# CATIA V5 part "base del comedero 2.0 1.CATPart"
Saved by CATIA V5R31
Part number: base del comedero 2.0
Bounding box of the stored display mesh (mm): x -244 to 244, y -89 to 89, z 0 to 15
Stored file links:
  C:\Users\189361\Desktop\piezas del comedero\piezas del comedero\base del comedero 2.0 1.CATPart
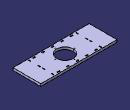
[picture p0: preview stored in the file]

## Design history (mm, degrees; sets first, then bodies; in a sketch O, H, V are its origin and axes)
Body1 (main body)
  Sketch1 on xy-plane, origin (0, 0, 0), H (1, 0, 0), V (0, 1, 0)
    circle A1 centre (0, 0) radius 53
    circle A2 centre (0, 62.25) radius 2.25
    point P1 (0, 62.25)
    circle A3 centre (62.25, 0) radius 2.25
    point P2 (62.25, 0)
    circle A4 centre (0, -62.25) radius 2.25
    circle A5 centre (-62.25, 0) radius 2.25
    line L1 (-164, 89) -> (164, 89)
    line L2 (164, 89) -> (164, -89)
    line L3 (164, -89) -> (-164, -89)
    line L4 (-164, -89) -> (-164, 89)
    point P9 (-153.3, 81.6)
    line L5 (-153.3, 81.6) -> (-150, 81.6)
    line L6 (-150, 81.6) -> (-150, 66.6)
    line L7 (-150, 66.6) -> (-153.3, 66.6)
    line L8 (-153.3, 66.6) -> (-153.3, 81.6)
    point P10 (-150, 81.6)
    point P11 (-150, 66.6)
    point P12 (-153.3, 66.6)
    point P13 (-127.5, 81.6)
    line L9 (-127.5, 81.6) -> (-112.5, 81.6)
    line L10 (-112.5, 81.6) -> (-112.5, 75)
    line L11 (-112.5, 75) -> (-127.5, 75)
    line L12 (-127.5, 75) -> (-127.5, 81.6)
    point P14 (-112.5, 81.6)
    point P15 (-112.5, 75)
    point P16 (-127.5, 75)
    construction line L13 (-120, 64.0681) -> (-120, 97.6973)
    point P17 (-120, 64.0681)
    point P18 (-120, 97.6973)
    construction line L14 (-169.6083, 74.1) -> (-149.5524, 74.1)
    point P19 (-169.6083, 74.1)
    point P20 (-149.5524, 74.1)
    construction line L15 (-166.5695, 44.1) -> (-141.0438, 44.1)
    point P21 (-166.5695, 44.1)
    point P22 (-141.0438, 44.1)
    point P23 (-153.3, 6.6)
    point P24 (-150, 6.6)
    point P25 (-150, 21.6)
    point P26 (-153.3, 21.6)
    point P27 (-169.6083, 14.1)
    point P28 (-149.5524, 14.1)
    construction line L16 (-169.6083, 14.1) -> (-149.5524, 14.1)
    line L17 (-153.3, 6.6) -> (-150, 6.6)
    line L18 (-150, 6.6) -> (-150, 21.6)
    line L19 (-150, 21.6) -> (-153.3, 21.6)
    line L20 (-153.3, 21.6) -> (-153.3, 6.6)
    axis line L21 (-90, 102.762) -> (-90, 66.7018)
    point P29 (-90, 102.762)
    point P30 (-90, 66.7018)
    point P31 (-52.5, 81.6)
    point P32 (-67.5, 81.6)
    point P33 (-67.5, 75)
    point P34 (-52.5, 75)
    point P35 (-60, 97.6973)
    point P36 (-60, 64.0681)
    construction line L22 (-60, 64.0681) -> (-60, 97.6973)
    line L23 (-52.5, 81.6) -> (-67.5, 81.6)
    line L24 (-67.5, 81.6) -> (-67.5, 75)
    line L25 (-67.5, 75) -> (-52.5, 75)
    line L26 (-52.5, 75) -> (-52.5, 81.6)
    point P37 (-153.3, -81.6)
    point P38 (-150, -81.6)
    point P39 (-150, -66.6)
    point P40 (-153.3, -66.6)
    point P41 (-149.5524, -74.1)
    point P42 (-169.6083, -74.1)
    construction line L27 (-169.6083, -74.1) -> (-149.5524, -74.1)
    point P43 (-141.0438, -44.1)
    point P44 (-166.5695, -44.1)
    construction line L28 (-166.5695, -44.1) -> (-141.0438, -44.1)
    point P45 (-153.3, -6.6)
    point P46 (-150, -6.6)
    point P47 (-150, -21.6)
    point P48 (-153.3, -21.6)
    point P49 (-169.6083, -14.1)
    point P50 (-149.5524, -14.1)
    construction line L29 (-169.6083, -14.1) -> (-149.5524, -14.1)
    line L30 (-153.3, -81.6) -> (-150, -81.6)
    line L31 (-150, -81.6) -> (-150, -66.6)
    line L32 (-150, -66.6) -> (-153.3, -66.6)
    line L33 (-153.3, -66.6) -> (-153.3, -81.6)
    line L34 (-153.3, -6.6) -> (-150, -6.6)
    line L35 (-150, -6.6) -> (-150, -21.6)
    line L36 (-150, -21.6) -> (-153.3, -21.6)
    line L37 (-153.3, -21.6) -> (-153.3, -6.6)
    point P51 (153.3, 6.6)
    point P52 (150, 6.6)
    point P53 (150, 21.6)
    point P54 (153.3, 21.6)
    point P55 (149.5524, 14.1)
    point P56 (153.3, -81.6)
    point P57 (150, -81.6)
    point P58 (150, -66.6)
    point P59 (153.3, -66.6)
    point P60 (149.5524, -74.1)
    point P61 (153.3, -6.6)
    point P62 (150, -6.6)
    point P63 (150, -21.6)
    point P64 (153.3, -21.6)
    point P65 (149.5524, -14.1)
    line L38 (153.3, 6.6) -> (150, 6.6)
    line L39 (150, 6.6) -> (150, 21.6)
    line L40 (150, 21.6) -> (153.3, 21.6)
    line L41 (153.3, 21.6) -> (153.3, 6.6)
    line L42 (153.3, -81.6) -> (150, -81.6)
    line L43 (150, -81.6) -> (150, -66.6)
    line L44 (150, -66.6) -> (153.3, -66.6)
    line L45 (153.3, -66.6) -> (153.3, -81.6)
    line L46 (153.3, -6.6) -> (150, -6.6)
    line L47 (150, -6.6) -> (150, -21.6)
    line L48 (150, -21.6) -> (153.3, -21.6)
    line L49 (153.3, -21.6) -> (153.3, -6.6)
    point P66 (153.3, 81.6)
    point P67 (150, 81.6)
    point P68 (149.5524, 74.1)
    line L50 (153.3, 81.6) -> (150, 81.6)
    point P69 (150, 66.6)
    line L51 (150, 81.6) -> (150, 66.6)
    point P70 (153.3, 66.6)
    line L52 (153.3, 66.6) -> (153.3, 81.6)
    line L53 (150, 66.6) -> (153.3, 66.6)
    point P71 (127.5, 81.6)
    point P72 (112.5, 81.6)
    point P73 (112.5, 75)
    point P74 (127.5, 75)
    point P75 (120, 97.6973)
    point P76 (120, 64.0681)
    construction line L54 (120, 64.0681) -> (120, 97.6973)
    point P77 (90, 66.7018)
    point P78 (90, 102.762)
    construction line L55 (90, 102.762) -> (90, 66.7018)
    point P79 (52.5, 81.6)
    point P80 (67.5, 81.6)
    point P81 (67.5, 75)
    point P82 (52.5, 75)
    point P83 (60, 97.6973)
    point P84 (60, 64.0681)
    construction line L56 (60, 64.0681) -> (60, 97.6973)
    line L57 (127.5, 81.6) -> (112.5, 81.6)
    line L58 (112.5, 81.6) -> (112.5, 75)
    line L59 (112.5, 75) -> (127.5, 75)
    line L60 (127.5, 75) -> (127.5, 81.6)
    line L61 (52.5, 81.6) -> (67.5, 81.6)
    line L62 (67.5, 81.6) -> (67.5, 75)
    line L63 (67.5, 75) -> (52.5, 75)
    line L64 (52.5, 75) -> (52.5, 81.6)
    point P85 (-127.5, -81.6)
    point P86 (-112.5, -81.6)
    point P87 (-112.5, -75)
    point P88 (-127.5, -75)
    point P89 (-52.5, -81.6)
    point P90 (-67.5, -81.6)
    point P91 (-67.5, -75)
    point P92 (-52.5, -75)
    point P93 (127.5, -81.6)
    point P94 (112.5, -81.6)
    point P95 (112.5, -75)
    point P96 (127.5, -75)
    point P97 (52.5, -81.6)
    point P98 (67.5, -81.6)
    point P99 (67.5, -75)
    point P100 (52.5, -75)
    line L65 (-127.5, -81.6) -> (-112.5, -81.6)
    line L66 (-112.5, -81.6) -> (-112.5, -75)
    line L67 (-112.5, -75) -> (-127.5, -75)
    line L68 (-127.5, -75) -> (-127.5, -81.6)
    line L69 (-52.5, -81.6) -> (-67.5, -81.6)
    line L70 (-67.5, -81.6) -> (-67.5, -75)
    line L71 (-67.5, -75) -> (-52.5, -75)
    line L72 (-52.5, -75) -> (-52.5, -81.6)
    line L73 (127.5, -81.6) -> (112.5, -81.6)
    line L74 (112.5, -81.6) -> (112.5, -75)
    line L75 (112.5, -75) -> (127.5, -75)
    line L76 (127.5, -75) -> (127.5, -81.6)
    line L77 (52.5, -81.6) -> (67.5, -81.6)
    line L78 (67.5, -81.6) -> (67.5, -75)
    line L79 (67.5, -75) -> (52.5, -75)
    line L80 (52.5, -75) -> (52.5, -81.6)
    point P101 (-7.5, 81.6)
    line L81 (-7.5, 81.6) -> (7.5, 81.6)
    line L82 (7.5, 81.6) -> (7.5, 75.6)
    line L83 (7.5, 75.6) -> (-7.5, 75.6)
    line L84 (-7.5, 75.6) -> (-7.5, 81.6)
    point P102 (7.5, 81.6)
    point P103 (7.5, 75.6)
    point P104 (-7.5, 75.6)
    point P105 (-7.5, -81.6)
    point P106 (7.5, -81.6)
    point P107 (7.5, -75.6)
    point P108 (-7.5, -75.6)
    line L85 (-7.5, -81.6) -> (7.5, -81.6)
    line L86 (7.5, -81.6) -> (7.5, -75.6)
    line L87 (7.5, -75.6) -> (-7.5, -75.6)
    line L88 (-7.5, -75.6) -> (-7.5, -81.6)
    radius A1 = 53
    radius A2 = 2.25
    distance A1 A2 = 7
    distance A1 A3 = 7
    length L1 = 328
    length L2 = 178
    distance H L1 = 89
    distance V L2 = 164
    length L5 = 3.3
    length L8 = 15
    length L9 = 15
    length L12 = 6.6
    distance L8 L4 = 10.7
    distance L9 L1 = 7.4
    distance L13 L10 = 7.5
    distance L13 L6 = 30
    distance L14 L5 = 7.5
    distance L15 L14 = 30
    distance L13 L21 = 30
    length L81 = 15
    length L84 = 6
    distance V L82 = 7.5
    distance L31 L43 = 300 (reference)
    distance L75 L59 = 150 (reference)
    distance L73 L57 = 163.2 (reference)
    distance V A3 = 64.5 (reference)
    distance L75 L59 = 150 (reference)
    distance P2 O = 62.25 (reference)
    coincidence: P1 V, P2 H, L5 L9, L81 L23
    equal size: A2 A3
    symmetry: A2 A4 H, A3 A5 V, P9 P23 L15, P10 P24 L15, P11 P25 L15, P12 P26 L15, P19 P27 L15, P20 P28 L15, L14 L16 L15, L5 L17 L15, L6 L18 L15, L7 L19 L15, L8 L20 L15, P13 P31 L21, P14 P32 L21, P15 P33 L21, P16 P34 L21, P18 P35 L21, P17 P36 L21, L13 L22 L21, L9 L23 L21, L10 L24 L21, L11 L25 L21, L12 L26 L21, P9 P37 H, P10 P38 H, P11 P39 H, P12 P40 H, P20 P41 H, P19 P42 H, L14 L27 H, P22 P43 H, P21 P44 H, L15 L28 H, P23 P45 H, P24 P46 H, P25 P47 H, P26 P48 H, P27 P49 H, P28 P50 H, L16 L29 H, L5 L30 H, L6 L31 H, L7 L32 H, L8 L33 H, L17 L34 H, L18 L35 H, L19 L36 H, L20 L37 H, P23 P51 V, P24 P52 V, P25 P53 V, P26 P54 V, P28 P55 V, P37 P56 V, P38 P57 V, P39 P58 V, P40 P59 V, P41 P60 V, P45 P61 V, P46 P62 V, P47 P63 V, P48 P64 V, P50 P65 V, L17 L38 V, L18 L39 V, L19 L40 V, L20 L41 V, L30 L42 V, L31 L43 V, L32 L44 V, L33 L45 V, L34 L46 V, L35 L47 V, L36 L48 V, L37 L49 V, P9 P66 V, P10 P67 V, P20 P68 V, L5 L50 V, P11 P69 V, L6 L51 V, P12 P70 V, L8 L52 V, L7 L53 V, P13 P71 V, P14 P72 V, P15 P73 V, P16 P74 V, P18 P75 V, P17 P76 V, L13 L54 V, P30 P77 V, P29 P78 V, L21 L55 V, P31 P79 V, P32 P80 V, P33 P81 V, P34 P82 V, P35 P83 V, P36 P84 V, L22 L56 V, L9 L57 V, L10 L58 V, L11 L59 V, L12 L60 V, L23 L61 V, L24 L62 V, L25 L63 V, L26 L64 V, P13 P85 H, P14 P86 H, P15 P87 H, P16 P88 H, P31 P89 H, P32 P90 H, P33 P91 H, P34 P92 H, P71 P93 H, P72 P94 H, P73 P95 H, P74 P96 H, P79 P97 H, P80 P98 H, P81 P99 H, P82 P100 H, L9 L65 H, L10 L66 H, L11 L67 H, L12 L68 H, L23 L69 H, L24 L70 H, L25 L71 H, L26 L72 H, L57 L73 H, L58 L74 H, L59 L75 H, L60 L76 H, L61 L77 H, L62 L78 H, L63 L79 H, L64 L80 H, P101 P105 H, P102 P106 H, P103 P107 H, P104 P108 H, L81 L85 H, L82 L86 H, L83 L87 H, L84 L88 H
    horizontal: L1 H, L3 H, L5 H, L7 H, L9 H, L11 H, L14 H, L15 H, L81 H, L83 H
    vertical: L2 V, L4 V, L6 V, L8 V, L10 V, L12 V, L13 V, L21 V, L82 V, L84 V
  Pad1: profile Sketch1, direction (0, 0, 1), length 15
  Sketch2 on start face of Pad1, origin (0, 0, 0), H (1, 0, 0), V (0, -1, 0)
    point P1 (-164, 89)
    line L1 (-164, 89) -> (-244, 89)
    line L2 (-244, 89) -> (-244, -89)
    line L3 (-244, -89) -> (-164, -89)
    line L4 (-164, -89) -> (-164, 89)
    point P2 (-244, 89)
    point P3 (-244, -89)
    point P4 (-164, -89)
    reference projected line E1 (164, -89) -> (-164, -89) from edge [start face of Pad1 | face of Pad1 from Sketch1.L1]
    reference projected line E2 (-164, 89) -> (164, 89) from edge [start face of Pad1 | face of Pad1 from Sketch1.L3]
    reference projected line E3 (-164, -89) -> (-164, 89) from edge [start face of Pad1 | face of Pad1 from Sketch1.L4]
    point P5 (164, -89)
    point P6 (244, -89)
    line L5 (244, -89) -> (164, -89)
    point P7 (164, 89)
    line L6 (164, -89) -> (164, 89)
    point P8 (244, 89)
    line L7 (244, 89) -> (244, -89)
    line L8 (164, 89) -> (244, 89)
    length L1 = 80
    horizontal: L1 H, L3 H
    vertical: L2 V, L4 V
    coincidence: L3 E1, L1 E2, L4 E3
    symmetry: P4 P5 V, P3 P6 V, L3 L5 V, P1 P7 V, L4 L6 V, P2 P8 V, L2 L7 V, L1 L8 V
  Pad2: profile Sketch2, direction (0, 0, 1), length 15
